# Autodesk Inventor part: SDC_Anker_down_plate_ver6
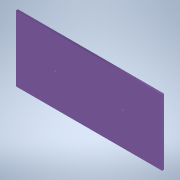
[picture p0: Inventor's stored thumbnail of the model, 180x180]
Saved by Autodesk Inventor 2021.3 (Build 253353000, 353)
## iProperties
Created: 2022-01
Part Number: SDC_Anker_down_plate_ver6
Material: アルミニウム 6061
Document SubType Name: Modeling
Designer: kengo
Density: 2.7 g/cm^3
Appearance: アルミニウム - フラット
Author: kengo
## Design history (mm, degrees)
sketch "スケッチ1"
  geometry: L1 (-589.671, 316.432)-(590.329, 316.432); L2 (590.329, 316.432)-(590.329, -283.568); L3 (590.329, -283.568)-(-589.671, -283.568); L4 (-589.671, -283.568)-(-589.671, 316.432); 1 further point
  constraints: 8 end point, 2 parallel, 1 horizontal, 1 perpendicular
  dimensions: "d0" = 600 distance of L3.end L1.start; "d1" = 1180 distance of L1.start L1.end
extrude "押し出し1" new body sketch "スケッチ1" distance "d2" = 15; taper "d3" = 0 deg
sketch "スケッチ4"
  geometry: L1 (-589.671, 316.432)-(-589.671, -283.568) reference; L2 (590.329, -283.568)-(590.329, 316.432) reference; L3 (-589.671, 261.432)-(590.329, 261.432); L4 (590.329, 261.432)-(590.329, -228.568); L5 (590.329, -228.568)-(-589.671, -228.568); L6 (-589.671, -228.568)-(-589.671, 261.432); L7 (590.329, 316.432)-(-589.671, 316.432) reference; L8 (-589.671, -283.568)-(590.329, -283.568) reference; L9 (-589.671, 316.432)-(590.329, 316.432); L10 (590.329, 316.432)-(590.329, -283.568); L11 (590.329, -283.568)-(-589.671, -283.568); L12 (-589.671, -283.568)-(-589.671, 316.432); 3 further points
  constraints: 16 end point, 4 parallel, 2 horizontal, 2 perpendicular, 2 point on line
  dimensions: "d58" = 490 distance between parallel lines of L5 L3; "d59" = 55 distance between parallel lines of L7 L3
extrude "押し出し2" cut sketch "スケッチ4" distance "d60" = 30; taper "d61" = 0 deg
sketch "スケッチ7" dims "d101" = 10, "d108" = 10
  geometry: L1 (590.329, 261.432)-(-589.671, 261.432) reference; L2 (-589.671, 261.432)-(-589.671, -228.568) reference; L3 (-589.671, 261.432)-(-589.671, -228.568); C1 r 3.324 at (-342.171, 138.932) reference; 5 further points
  constraints: 2 end point, 1 collinear, 1 horizontal, 1 vertical, 3 other
  dimensions: "d94" = 130 distance from line of L1 point (-204.671, 131.432); "d95" = 137.5 horizontal distance of point (-204.671, 131.432) C1.centre; "d98" = 500 distance of point (-204.671, 131.432) point (295.329, 131.432); "d105" = 230 distance of point (295.329, 131.432) point (295.329, -98.568)
hole "穴4" sketch "スケッチ7" diameter "d110" = 6.647; stored, may be unused: countersink angle "d114" = 90 deg, drill point angle "d116" = 118 deg; dims "d111" = 15, "d112" = 4, "d113" = 2, "d115" = 22.2
sketch "スケッチ8"
  geometry: L1 (-589.671, 261.432)-(590.329, 261.432) reference; L2 (590.329, -228.568)-(-589.671, -228.568) reference; L3 (-499.671, 261.432)-(-589.671, 261.432); L4 (-589.671, 261.432)-(-589.671, -228.568); L5 (-589.671, -228.568)-(-499.671, -228.568); L6 (-499.671, -228.568)-(-499.671, 261.432); 3 further points
  constraints: 8 end point, 2 parallel, 1 horizontal, 1 perpendicular, 1 point on line
  dimensions: "d119" = 90 distance between parallel lines of L4 L6
extrude "押し出し4" cut sketch "スケッチ8" distance "d120" = 20; taper "d121" = 0 deg
sketch "スケッチ9"
  geometry: L1 (590.329, 261.432)-(-499.671, 261.432) reference; L2 (590.329, -228.568)-(590.329, 261.432) reference; 2 further points
  dimensions: "d122" = 245 distance from line of L1 point (45.329, 16.432); "d123" = 545 distance from line of L2 point (45.329, 16.432)
hole "穴5" sketch "スケッチ9" at (45.329, 16.432) diameter "d124" = 8.376; stored, may be unused: countersink angle "d128" = 90 deg, drill point angle "d130" = 118 deg; dims "d125" = 20, "d126" = 4, "d127" = 2, "d129" = 51.2
sketch "スケッチ10"
  geometry: L1 (-499.671, -228.568)-(590.329, -228.568) reference; C1 r 3.324 at (-204.671, 131.432) reference; C2 r 3.324 at (295.329, 131.432) reference; 3 further points
  dimensions: "d131" = 0 horizontal distance of C1.centre point (-204.671, 16.432); "d132" = 245 distance from line of L1 point (-204.671, 16.432); "d133" = 245 distance from line of L1 point (295.329, 16.432); "d134" = 0 horizontal distance of C2.centre point (295.329, 16.432)
hole "穴6" sketch "スケッチ10" at (-204.671, 16.432), (295.329, 16.432) diameter "d135" = 18; stored, may be unused: countersink angle "d139" = 90 deg, drill point angle "d141" = 118 deg; dims "d136" = 6, "d137" = 4, "d138" = 2, "d140" = 22.2
node "ソリッド1"
